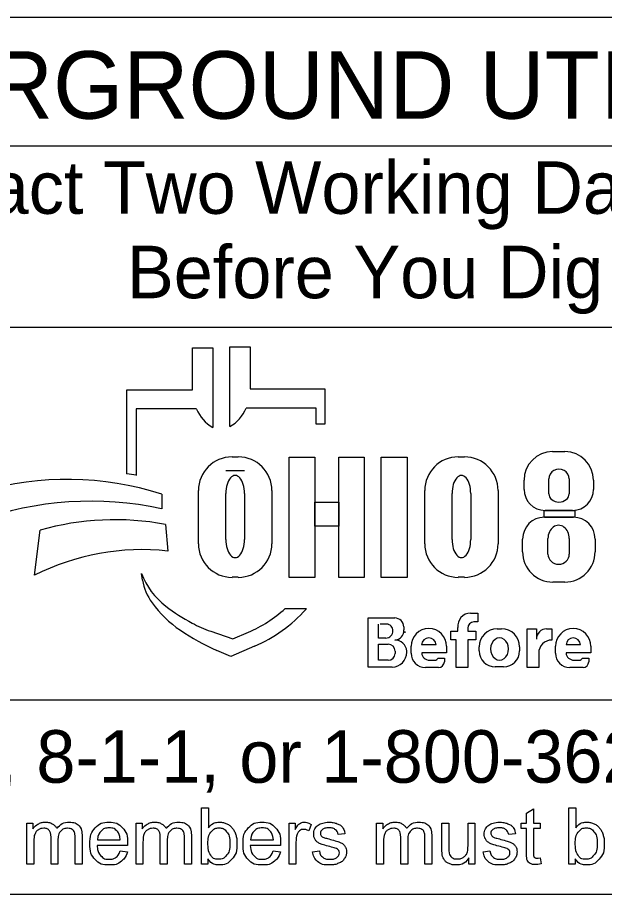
# Model space of a CAD drawing. Extents: x 0 to 64.8, y -5 to 22.
# Drawn here: x 36.856 to 38.421, y 2.143 to 4.48 of the extents above; entities that cross this region are included whole.
import ezdxf

# ---------------------------------------------------------------- set-up
doc = ezdxf.new("R2010")
doc.units = 0
doc.layers.add('SH_Data', color=7, linetype='Continuous')
doc.layers.add('SH_Text', color=7, linetype='Continuous')

msp = doc.modelspace()

# ---------------------------------------------------------------- linework, layer by layer
at = {"layer": 'SH_Data'}
for p, q in [((40.2169, 4.4803), (35.9669, 4.4803)), ((35.9669, 4.1387), (40.2169, 4.1387)), ((35.9669, 3.6553), (40.2169, 3.6553)), ((40.2169, 2.6607), (35.9669, 2.6607)), ((40.2169, 2.1428), (35.9669, 2.1428))]:
    msp.add_line(p, q, dxfattribs=at)
at = {"layer": 'SH_Text'}
for p, q in [((37.3229, 3.4883), (37.3229, 3.5998)), ((37.3229, 3.5998), (37.3766, 3.5998)), ((37.3766, 3.5998), (37.3766, 3.3877)), ((37.4222, 3.39), (37.4222, 3.6021)), ((37.4222, 3.6021), (37.4759, 3.6021)), ((37.4759, 3.6021), (37.4759, 3.4906)), ((37.147, 3.2644), (37.147, 3.4883)), ((37.147, 3.4883), (37.3229, 3.4883)), ((37.4759, 3.4906), (37.6751, 3.4906)), ((37.6751, 3.4906), (37.6751, 3.3968)), ((37.1722, 3.4369), (37.1722, 3.26)), ((37.3333, 3.4369), (37.1722, 3.4369)), ((37.6518, 3.4392), (37.4655, 3.4392)), ((37.6518, 3.3968), (37.6518, 3.4392)), ((37.6751, 3.3968), (37.6518, 3.3968)), ((38.2825, 3.3231), (38.3152, 3.3231)), ((37.4279, 3.3091), (37.4445, 3.3091)), ((38.031, 3.3091), (38.0475, 3.3091)), ((37.4612, 3.2721), (37.4114, 3.2721)), ((38.2723, 3.2111), (38.2723, 3.2504)), ((38.3265, 3.2504), (38.3265, 3.2111)), ((38.2062, 3.2225), (38.2062, 3.2468)), ((38.3915, 3.2468), (38.3915, 3.2225)), ((37.2403, 3.2097), (37.2403, 3.1709)), ((37.3385, 3.0776), (37.3385, 3.2196)), ((37.4114, 3.089), (37.4114, 3.2114)), ((37.4612, 3.2114), (37.4612, 3.089)), ((37.5339, 3.2196), (37.5339, 3.0776)), ((37.9415, 3.0776), (37.9415, 3.2196)), ((38.0144, 3.089), (38.0144, 3.2114)), ((38.0642, 3.2114), (38.0642, 3.089)), ((38.137, 3.2196), (38.137, 3.0776)), ((38.3355, 3.1665), (38.2622, 3.1665)), ((38.2604, 3.1482), (38.3377, 3.1482)), ((36.9014, 2.9936), (36.9161, 3.1137)), ((37.2502, 3.1291), (37.2565, 3.0582)), ((38.2025, 3.0563), (38.2025, 3.0903)), ((38.27, 3.0503), (38.27, 3.0912)), ((38.3268, 3.0912), (38.3268, 3.0503)), ((38.3956, 3.0903), (38.3956, 3.0563)), ((37.1891, 2.9807), (37.1861, 2.9986)), ((37.4445, 2.9882), (37.4279, 2.9882)), ((38.0475, 2.9882), (38.031, 2.9882)), ((38.3146, 2.9753), (38.2834, 2.9753)), ((37.5694, 2.9048), (37.6268, 2.9048)), ((37.7907, 2.749), (37.7907, 2.8798)), ((37.7907, 2.8798), (37.8619, 2.8798)), ((38.0633, 2.8926), (38.0827, 2.8926)), ((38.0827, 2.8926), (38.0827, 2.8696)), ((37.8187, 2.8263), (37.8187, 2.8632)), ((37.8439, 2.8632), (37.8226, 2.8632)), ((37.8856, 2.856), (37.8856, 2.8481)), ((38.03, 2.8442), (38.03, 2.8546)), ((38.0561, 2.8526), (38.0561, 2.8442)), ((38.0827, 2.8691), (38.0726, 2.8691)), ((37.371, 2.8444), (37.4304, 2.8239)), ((37.4304, 2.8239), (37.4714, 2.8417)), ((38.0107, 2.8212), (38.0107, 2.8442)), ((38.0107, 2.8442), (38.03, 2.8442)), ((38.0561, 2.8442), (38.0777, 2.8442)), ((38.0777, 2.8442), (38.0777, 2.8212)), ((38.1345, 2.8508), (38.1466, 2.8508)), ((38.2148, 2.7478), (38.2148, 2.8505)), ((38.2148, 2.8505), (38.2393, 2.8505)), ((38.2393, 2.8505), (38.2393, 2.8237)), ((38.2665, 2.8505), (38.2804, 2.8505)), ((38.2804, 2.8505), (38.2804, 2.8209)), ((37.8381, 2.8263), (37.8187, 2.8263)), ((37.8187, 2.7669), (37.8187, 2.8097)), ((37.8187, 2.8097), (37.8442, 2.8097)), ((37.9718, 2.8082), (37.9333, 2.8082)), ((38.0256, 2.8212), (38.0107, 2.8212)), ((38.0256, 2.7478), (38.0256, 2.8212)), ((38.0777, 2.8212), (38.0561, 2.8212)), ((38.0561, 2.8212), (38.0561, 2.7478)), ((38.3568, 2.8082), (38.3182, 2.8082)), ((37.4244, 2.7769), (37.387, 2.7934)), ((37.4877, 2.8044), (37.4244, 2.7769)), ((37.8623, 2.7916), (37.8623, 2.7853)), ((37.8937, 2.7887), (37.8937, 2.7884)), ((37.9053, 2.7858), (37.9053, 2.8042)), ((37.9998, 2.7866), (37.9334, 2.7866)), ((37.9998, 2.8042), (37.9998, 2.7866)), ((38.0867, 2.7922), (38.0867, 2.8029)), ((38.1944, 2.8029), (38.1944, 2.7922)), ((38.2453, 2.786), (38.2453, 2.7478)), ((38.2902, 2.7858), (38.2902, 2.8042)), ((38.3847, 2.7866), (38.3183, 2.7866)), ((38.3847, 2.8042), (38.3847, 2.7866)), ((37.844, 2.7669), (37.8187, 2.7669)), ((37.9543, 2.7673), (37.9684, 2.7673)), ((37.977, 2.7729), (37.9938, 2.7729)), ((37.9938, 2.7729), (37.9938, 2.7631)), ((38.3392, 2.7673), (38.3533, 2.7673)), ((38.3619, 2.7729), (38.3788, 2.7729)), ((38.3788, 2.7729), (38.3788, 2.7631)), ((37.8544, 2.749), (37.7907, 2.749)), ((37.9786, 2.7478), (37.9432, 2.7478)), ((38.0561, 2.7478), (38.0256, 2.7478)), ((38.1517, 2.7494), (38.1295, 2.7494)), ((38.2453, 2.7478), (38.2148, 2.7478)), ((38.3635, 2.7478), (38.3281, 2.7478))]:
    msp.add_line(p, q, dxfattribs=at)
for points in [[(37.5804, 3.3081), (37.6483, 3.3081), (37.6483, 2.9881), (37.5804, 2.9881)], [(37.7125, 3.3081), (37.7805, 3.3081), (37.7805, 2.9881), (37.7125, 2.9881)], [(37.8258, 3.3081), (37.8946, 3.3081), (37.8946, 2.9881), (37.8258, 2.9881)], [(37.6483, 3.1882), (37.7125, 3.1882), (37.7125, 3.1242), (37.6483, 3.1242)], [(38.26, 3.1665), (38.3417, 3.1665), (38.3417, 3.1481), (38.26, 3.1481)]]:
    msp.add_lwpolyline(points, close=True, dxfattribs=at)
for points in [[(37.3637, 2.2239), (37.3467, 2.2239), (37.3467, 2.3741), (37.3651, 2.3741), (37.3651, 2.3206)], [(38.2127, 2.2558), (38.2127, 2.3185), (38.199, 2.3185), (38.199, 2.3328), (38.2127, 2.3328), (38.2127, 2.3597), (38.2311, 2.3708), (38.2311, 2.3328), (38.2495, 2.3328), (38.2495, 2.3185), (38.2311, 2.3185), (38.2311, 2.2547)], [(38.3428, 2.2239), (38.3257, 2.2239), (38.3257, 2.3741), (38.3442, 2.3741), (38.3442, 2.3206)], [(36.8806, 2.2239), (36.8806, 2.3328), (36.8971, 2.3328), (36.8971, 2.3174)], [(37.172, 2.2239), (37.172, 2.3328), (37.1885, 2.3328), (37.1885, 2.3174)], [(37.5798, 2.2239), (37.5798, 2.3328), (37.5964, 2.3328), (37.5964, 2.3163)], [(37.6388, 2.3293), (37.6324, 2.3122)], [(37.813, 2.2239), (37.813, 2.3328), (37.8295, 2.3328), (37.8295, 2.3174)], [(37.9873, 2.2654), (37.9873, 2.3328), (38.0057, 2.3328), (38.0057, 2.2724)], [(38.057, 2.2745), (38.057, 2.3328), (38.0754, 2.3328), (38.0754, 2.2239), (38.059, 2.2239)], [(36.9637, 2.2871), (36.9637, 2.2239), (36.9453, 2.2239), (36.9453, 2.2946)], [(37.0281, 2.2986), (37.0281, 2.2239), (37.0097, 2.2239), (37.0097, 2.2924)], [(37.2551, 2.2871), (37.2551, 2.2239), (37.2367, 2.2239), (37.2367, 2.2946)], [(37.3195, 2.2986), (37.3195, 2.2239), (37.3011, 2.2239), (37.3011, 2.2924)], [(37.7288, 2.3046), (37.7107, 2.3022)], [(37.8961, 2.2871), (37.8961, 2.2239), (37.8777, 2.2239), (37.8777, 2.2946)], [(37.9605, 2.2986), (37.9605, 2.2239), (37.9421, 2.2239), (37.9421, 2.2924)], [(38.1834, 2.3046), (38.1653, 2.3022)], [(36.8991, 2.2803), (36.8991, 2.2239), (36.8806, 2.2239)], [(37.1494, 2.2736), (37.0682, 2.2736)], [(37.0693, 2.2887), (37.13, 2.2887)], [(37.1904, 2.2803), (37.1904, 2.2239), (37.172, 2.2239)], [(37.5574, 2.2736), (37.4762, 2.2736)], [(37.4772, 2.2887), (37.538, 2.2887)], [(37.5982, 2.2809), (37.5982, 2.2239), (37.5798, 2.2239)], [(37.8314, 2.2803), (37.8314, 2.2239), (37.813, 2.2239)], [(37.1298, 2.2591), (37.1489, 2.2567)], [(37.5378, 2.2591), (37.5569, 2.2567)], [(37.6424, 2.2564), (37.6606, 2.2593)], [(38.097, 2.2564), (38.1152, 2.2593)], [(37.3637, 2.2375), (37.3637, 2.2239)], [(38.059, 2.2239), (38.059, 2.24)], [(38.2495, 2.2404), (38.2521, 2.2241)], [(38.3428, 2.2375), (38.3428, 2.2239)]]:
    msp.add_lwpolyline(points, dxfattribs=at)
for centre, radius, start, end in [((37.4247, 3.4736), 0.0985, 201.9296, 240.7469), ((37.3741, 3.476), 0.0985, 299.2531, 338.0704), ((38.2825, 3.2468), 0.0763, 90, 180), ((38.3152, 3.2468), 0.0763, 0, 90), ((37.4279, 3.2196), 0.0895, 90, 180), ((37.4445, 3.2196), 0.0895, 0, 90), ((38.031, 3.2196), 0.0895, 90, 180), ((38.0475, 3.2196), 0.0895, 0, 90), ((36.9891, 2.4302), 0.8191, 72.1402, 106.3144), ((37.0188, 2.4554), 0.8191, 79.2074, 81.0007), ((38.2622, 3.2225), 0.056, 180, 270), ((38.3355, 3.2225), 0.056, 270, 0), ((37.0521, 2.2991), 0.8919, 77.8238, 109.8274), ((37.116, 2.4094), 0.7322, 79.44, 105.8467), ((38.2604, 3.0903), 0.0579, 90, 180), ((38.3377, 3.0903), 0.0579, 0, 90), ((37.4279, 3.0776), 0.0895, 180, 270), ((37.4445, 3.0776), 0.0895, 270, 0), ((38.031, 3.0776), 0.0895, 180, 270), ((38.0475, 3.0776), 0.0895, 270, 0), ((37.1881, 2.4262), 0.6357, 83.8248, 116.8021), ((38.2834, 3.0563), 0.081, 180, 270), ((38.3146, 3.0563), 0.081, 270, 0), ((37.3735, 3.0707), 0.2008, 201.0457, 232.5314), ((37.3304, 3.0048), 0.1433, 189.6817, 216.0884), ((37.4641, 3.1022), 0.3088, 216.0884, 235.7167), ((37.566, 3.3219), 0.5173, 232.5314, 241.794), ((37.328, 3.1722), 0.3602, 293.4582, 312.0712), ((37.328, 3.1722), 0.401, 293.4582, 317.8286), ((37.8619, 2.856), 0.0238, 0, 90), ((38.0633, 2.859), 0.0335, 90, 187.5187), ((37.4808, 3.1631), 0.3371, 241.794, 250.9821), ((37.8399, 2.8463), 0.0169, 357.8325, 90), ((38.0726, 2.8526), 0.0165, 90, 180), ((37.6306, 3.3465), 0.6044, 235.7167, 246.2325), ((37.8381, 2.845), 0.0187, 270, 2.0582), ((37.8615, 2.8453), 0.0243, 270, 6.6529), ((37.8721, 2.8438), 0.0175, 347.4023, 0), ((37.9525, 2.8042), 0.0473, 0, 180), ((38.1345, 2.8029), 0.0478, 90, 180), ((38.1466, 2.8029), 0.0478, 0, 90), ((38.2662, 2.8237), 0.0269, 89.2449, 180), ((38.3374, 2.8042), 0.0473, 0, 180), ((37.8442, 2.7916), 0.0181, 0, 90), ((37.8616, 2.7889), 0.0321, 4.0748, 90), ((37.9526, 2.8072), 0.0193, 2.9632, 177.0368), ((38.2802, 2.786), 0.0349, 89.6033, 180), ((38.3375, 2.8072), 0.0193, 2.9632, 177.0368), ((37.844, 2.7853), 0.0184, 270, 0), ((37.8544, 2.7884), 0.0393, 270, 0), ((37.8607, 2.7887), 0.033, 0, 11.7502), ((37.9432, 2.7858), 0.038, 180, 270), ((37.9543, 2.7883), 0.021, 184.827, 270), ((38.1295, 2.7922), 0.0428, 180, 270), ((38.1517, 2.7922), 0.0428, 270, 0), ((38.3281, 2.7858), 0.038, 180, 270), ((38.3392, 2.7883), 0.021, 184.827, 270), ((37.9684, 2.7767), 0.00938, 270, 335.9979), ((37.9786, 2.7631), 0.0152, 270, 0), ((38.3533, 2.7767), 0.00938, 270, 335.9979), ((38.3635, 2.7631), 0.0152, 270, 0)]:
    msp.add_arc(centre, radius, start, end, dxfattribs=at)
for centre, major_axis, ratio, start_param, end_param in [((38.2994, 3.2504), (0.0271, 0), 0.969373, 0, 3.141593), ((37.4363, 3.2114), (0, 0.0484), 0.514403, 4.712389, 7.853982), ((38.0393, 3.2114), (0, 0.0484), 0.514403, 4.712389, 7.853982), ((38.2994, 3.2111), (0.0271, 0), 0.818453, 3.141593, 6.283185), ((38.2984, 3.0912), (0, 0.0358), 0.794529, 4.712389, 7.853982), ((37.4363, 3.089), (0, 0.0484), 0.514403, 1.570796, 4.712389), ((38.0393, 3.089), (0, 0.0484), 0.514403, 1.570796, 4.712389), ((38.2984, 3.0503), (0.0284, 0), 0.959837, 3.141593, 6.283185), ((38.141, 2.7976), (0, 0.029), 0.832186, 4.712389, 7.853982), ((38.141, 2.7976), (0, 0.0302), 0.797287, 1.570796, 4.712389)]:
    msp.add_ellipse(centre, major_axis=major_axis, ratio=ratio, start_param=start_param, end_param=end_param, dxfattribs=at)
for points in [[(36.8971, 2.3174), (36.9022, 2.3254), (36.9107, 2.3303), (36.9192, 2.3352), (36.9301, 2.3352), (36.9422, 2.3352), (36.9499, 2.3301), (36.9577, 2.3251), (36.9609, 2.3161), (36.9738, 2.3352), (36.9945, 2.3352), (37.0107, 2.3352), (37.0194, 2.3262), (37.0281, 2.3172), (37.0281, 2.2986)], [(36.9453, 2.2946), (36.9453, 2.3069), (36.9408, 2.313), (36.9363, 2.3191), (36.926, 2.3191), (36.9182, 2.3191), (36.9116, 2.315), (36.905, 2.311), (36.902, 2.3031), (36.8991, 2.2952), (36.8991, 2.2803)], [(37.0097, 2.2924), (37.0097, 2.3035), (37.0079, 2.3083), (37.0061, 2.3132), (37.0014, 2.3162), (36.9967, 2.3191), (36.9904, 2.3191), (36.9789, 2.3191), (36.9713, 2.3115), (36.9637, 2.3039), (36.9637, 2.2871)], [(37.1489, 2.2567), (37.1444, 2.24), (37.1322, 2.2307), (37.12, 2.2215), (37.101, 2.2215), (37.0772, 2.2215), (37.0632, 2.2362), (37.0492, 2.2509), (37.0492, 2.2774), (37.0492, 2.3049), (37.0634, 2.32), (37.0775, 2.3352), (37.1, 2.3352), (37.1218, 2.3352), (37.1357, 2.3203), (37.1495, 2.3055), (37.1495, 2.2785), (37.1495, 2.2769), (37.1494, 2.2736)], [(37.13, 2.2887), (37.1288, 2.3025), (37.1231, 2.3094), (37.1142, 2.3201), (37.1002, 2.3201), (37.0875, 2.3201), (37.0788, 2.3115), (37.0702, 2.303), (37.0693, 2.2887)], [(37.1885, 2.3174), (37.1936, 2.3254), (37.2021, 2.3303), (37.2106, 2.3352), (37.2215, 2.3352), (37.2336, 2.3352), (37.2413, 2.3301), (37.249, 2.3251), (37.2522, 2.3161), (37.2652, 2.3352), (37.2859, 2.3352), (37.3021, 2.3352), (37.3108, 2.3262), (37.3195, 2.3172), (37.3195, 2.2986)], [(37.2367, 2.2946), (37.2367, 2.3069), (37.2322, 2.313), (37.2276, 2.3191), (37.2174, 2.3191), (37.2096, 2.3191), (37.203, 2.315), (37.1964, 2.311), (37.1934, 2.3031), (37.1904, 2.2952), (37.1904, 2.2803)], [(37.3011, 2.2924), (37.3011, 2.3035), (37.2993, 2.3083), (37.2975, 2.3132), (37.2928, 2.3162), (37.2881, 2.3191), (37.2817, 2.3191), (37.2703, 2.3191), (37.2627, 2.3115), (37.2551, 2.3039), (37.2551, 2.2871)], [(37.3635, 2.2792), (37.3635, 2.2596), (37.3688, 2.2509), (37.3775, 2.2366), (37.3923, 2.2366), (37.4044, 2.2366), (37.4132, 2.2471), (37.422, 2.2576), (37.422, 2.2784), (37.422, 2.2998), (37.4135, 2.3099), (37.4051, 2.3201), (37.3931, 2.3201), (37.3811, 2.3201), (37.3723, 2.3096), (37.3635, 2.299), (37.3635, 2.2792)], [(37.3651, 2.3206), (37.3768, 2.3352), (37.3949, 2.3352), (37.4049, 2.3352), (37.4139, 2.3311), (37.4228, 2.3271), (37.4286, 2.3198), (37.4344, 2.3124), (37.4377, 2.3021), (37.441, 2.2918), (37.441, 2.28), (37.441, 2.252), (37.4271, 2.2368), (37.4133, 2.2215), (37.3939, 2.2215), (37.3747, 2.2215), (37.3637, 2.2375)], [(37.5569, 2.2567), (37.5523, 2.24), (37.5402, 2.2307), (37.528, 2.2215), (37.509, 2.2215), (37.4852, 2.2215), (37.4712, 2.2362), (37.4572, 2.2509), (37.4572, 2.2774), (37.4572, 2.3049), (37.4713, 2.32), (37.4855, 2.3352), (37.508, 2.3352), (37.5298, 2.3352), (37.5436, 2.3203), (37.5575, 2.3055), (37.5575, 2.2785), (37.5575, 2.2769), (37.5574, 2.2736)], [(37.538, 2.2887), (37.5368, 2.3025), (37.531, 2.3094), (37.5222, 2.3201), (37.5082, 2.3201), (37.4955, 2.3201), (37.4868, 2.3115), (37.4782, 2.303), (37.4772, 2.2887)], [(37.5964, 2.3163), (37.6027, 2.3278), (37.6081, 2.3315), (37.6135, 2.3352), (37.6199, 2.3352), (37.6292, 2.3352), (37.6388, 2.3293)], [(37.6324, 2.3122), (37.6257, 2.3162), (37.6189, 2.3162), (37.6129, 2.3162), (37.6081, 2.3125), (37.6033, 2.3089), (37.6013, 2.3024), (37.5982, 2.2926), (37.5982, 2.2809)], [(37.7107, 2.3022), (37.7095, 2.3106), (37.7036, 2.3153), (37.6977, 2.3201), (37.6869, 2.3201), (37.6742, 2.3201), (37.6688, 2.3159), (37.6633, 2.3116), (37.6633, 2.306), (37.6633, 2.3024), (37.6656, 2.2995), (37.6678, 2.2966), (37.6727, 2.2946), (37.6754, 2.2936), (37.689, 2.2899), (37.7086, 2.2847), (37.7163, 2.2813), (37.7241, 2.278), (37.7285, 2.2717), (37.7329, 2.2653), (37.7329, 2.2559), (37.7329, 2.2467), (37.7275, 2.2386), (37.7221, 2.2304), (37.712, 2.226), (37.7018, 2.2215), (37.689, 2.2215), (37.6677, 2.2215), (37.6566, 2.2303), (37.6455, 2.2391), (37.6424, 2.2564)], [(37.6606, 2.2593), (37.6621, 2.2483), (37.6692, 2.2425), (37.6762, 2.2366), (37.6888, 2.2366), (37.7016, 2.2366), (37.7077, 2.2418), (37.7139, 2.247), (37.7139, 2.254), (37.7139, 2.2602), (37.7085, 2.2638), (37.7047, 2.2663), (37.6896, 2.2701), (37.6693, 2.2752), (37.6614, 2.2789), (37.6536, 2.2827), (37.6495, 2.2893), (37.6455, 2.2959), (37.6455, 2.3038), (37.6455, 2.3111), (37.6488, 2.3173), (37.6521, 2.3235), (37.6579, 2.3276), (37.6622, 2.3308), (37.6696, 2.333), (37.6771, 2.3352), (37.6856, 2.3352), (37.6984, 2.3352), (37.7081, 2.3315), (37.7178, 2.3278), (37.7224, 2.3215), (37.727, 2.3152), (37.7288, 2.3046)], [(37.8295, 2.3174), (37.8346, 2.3254), (37.8431, 2.3303), (37.8516, 2.3352), (37.8625, 2.3352), (37.8746, 2.3352), (37.8823, 2.3301), (37.89, 2.3251), (37.8932, 2.3161), (37.9061, 2.3352), (37.9269, 2.3352), (37.9431, 2.3352), (37.9518, 2.3262), (37.9605, 2.3172), (37.9605, 2.2986)], [(37.8777, 2.2946), (37.8777, 2.3069), (37.8732, 2.313), (37.8686, 2.3191), (37.8584, 2.3191), (37.8506, 2.3191), (37.844, 2.315), (37.8374, 2.311), (37.8344, 2.3031), (37.8314, 2.2952), (37.8314, 2.2803)], [(37.9421, 2.2924), (37.9421, 2.3035), (37.9403, 2.3083), (37.9385, 2.3132), (37.9338, 2.3162), (37.9291, 2.3191), (37.9227, 2.3191), (37.9113, 2.3191), (37.9037, 2.3115), (37.8961, 2.3039), (37.8961, 2.2871)], [(38.1653, 2.3022), (38.164, 2.3106), (38.1582, 2.3153), (38.1523, 2.3201), (38.1415, 2.3201), (38.1288, 2.3201), (38.1233, 2.3159), (38.1179, 2.3116), (38.1179, 2.306), (38.1179, 2.3024), (38.1202, 2.2995), (38.1224, 2.2966), (38.1272, 2.2946), (38.13, 2.2936), (38.1435, 2.2899), (38.1631, 2.2847), (38.1709, 2.2813), (38.1786, 2.278), (38.1831, 2.2717), (38.1875, 2.2653), (38.1875, 2.2559), (38.1875, 2.2467), (38.1821, 2.2386), (38.1767, 2.2304), (38.1665, 2.226), (38.1564, 2.2215), (38.1436, 2.2215), (38.1223, 2.2215), (38.1112, 2.2303), (38.1, 2.2391), (38.097, 2.2564)], [(38.1152, 2.2593), (38.1167, 2.2483), (38.1237, 2.2425), (38.1308, 2.2366), (38.1434, 2.2366), (38.1562, 2.2366), (38.1623, 2.2418), (38.1685, 2.247), (38.1685, 2.254), (38.1685, 2.2602), (38.163, 2.2638), (38.1592, 2.2663), (38.1442, 2.2701), (38.1238, 2.2752), (38.116, 2.2789), (38.1082, 2.2827), (38.1041, 2.2893), (38.1, 2.2959), (38.1, 2.3038), (38.1, 2.3111), (38.1034, 2.3173), (38.1067, 2.3235), (38.1125, 2.3276), (38.1168, 2.3308), (38.1242, 2.333), (38.1316, 2.3352), (38.1402, 2.3352), (38.153, 2.3352), (38.1627, 2.3315), (38.1724, 2.3278), (38.177, 2.3215), (38.1816, 2.3152), (38.1834, 2.3046)], [(38.3426, 2.2792), (38.3426, 2.2596), (38.3479, 2.2509), (38.3566, 2.2366), (38.3714, 2.2366), (38.3834, 2.2366), (38.3922, 2.2471), (38.401, 2.2576), (38.401, 2.2784), (38.401, 2.2998), (38.3926, 2.3099), (38.3842, 2.3201), (38.3722, 2.3201), (38.3601, 2.3201), (38.3513, 2.3096), (38.3426, 2.299), (38.3426, 2.2792)], [(38.3442, 2.3206), (38.3558, 2.3352), (38.374, 2.3352), (38.384, 2.3352), (38.3929, 2.3311), (38.4019, 2.3271), (38.4077, 2.3198), (38.4135, 2.3124), (38.4168, 2.3021), (38.42, 2.2918), (38.42, 2.28), (38.42, 2.252), (38.4062, 2.2368), (38.3924, 2.2215), (38.373, 2.2215), (38.3537, 2.2215), (38.3428, 2.2375)], [(37.0682, 2.2736), (37.0692, 2.2557), (37.0784, 2.2462), (37.0875, 2.2366), (37.1011, 2.2366), (37.1113, 2.2366), (37.1184, 2.242), (37.1256, 2.2473), (37.1298, 2.2591)], [(37.4762, 2.2736), (37.4772, 2.2557), (37.4864, 2.2462), (37.4955, 2.2366), (37.5091, 2.2366), (37.5193, 2.2366), (37.5264, 2.242), (37.5336, 2.2473), (37.5378, 2.2591)], [(38.0057, 2.2724), (38.0057, 2.258), (38.0069, 2.253), (38.0086, 2.2457), (38.0142, 2.2416), (38.0199, 2.2374), (38.0282, 2.2374), (38.0364, 2.2374), (38.0437, 2.2417), (38.051, 2.2459), (38.054, 2.2533), (38.057, 2.2606), (38.057, 2.2745)], [(38.059, 2.24), (38.0463, 2.2215), (38.0245, 2.2215), (38.0149, 2.2215), (38.0065, 2.2252), (37.9982, 2.2289), (37.9941, 2.2345), (37.9901, 2.2401), (37.9884, 2.2482), (37.9873, 2.2536), (37.9873, 2.2654)], [(38.2521, 2.2241), (38.2444, 2.2224), (38.2382, 2.2224), (38.2282, 2.2224), (38.2227, 2.2256), (38.2172, 2.2288), (38.2149, 2.234), (38.2127, 2.2392), (38.2127, 2.2558)], [(38.2311, 2.2547), (38.2311, 2.2468), (38.2321, 2.2445), (38.233, 2.2423), (38.2352, 2.2409), (38.2374, 2.2396), (38.2415, 2.2396), (38.2445, 2.2396), (38.2495, 2.2404)]]:
    msp.add_open_spline(points, degree=3, dxfattribs=at)

# ---------------------------------------------------------------- texts
for s, height, p in [('UNDERGROUND UTILITIES', 0.18, (36.095, 4.2106)), ('Contact Two Working Days', 0.14, (36.3865, 3.9571)), ('Before You Dig', 0.14, (37.1477, 3.7321)), ('OHIO811, 8-1-1, or 1-800-362-2764', 0.14, (36.0114, 2.4406))]:
    msp.add_text(s, height=height, dxfattribs=at).set_placement(p)

doc.saveas('drawing.dxf')
